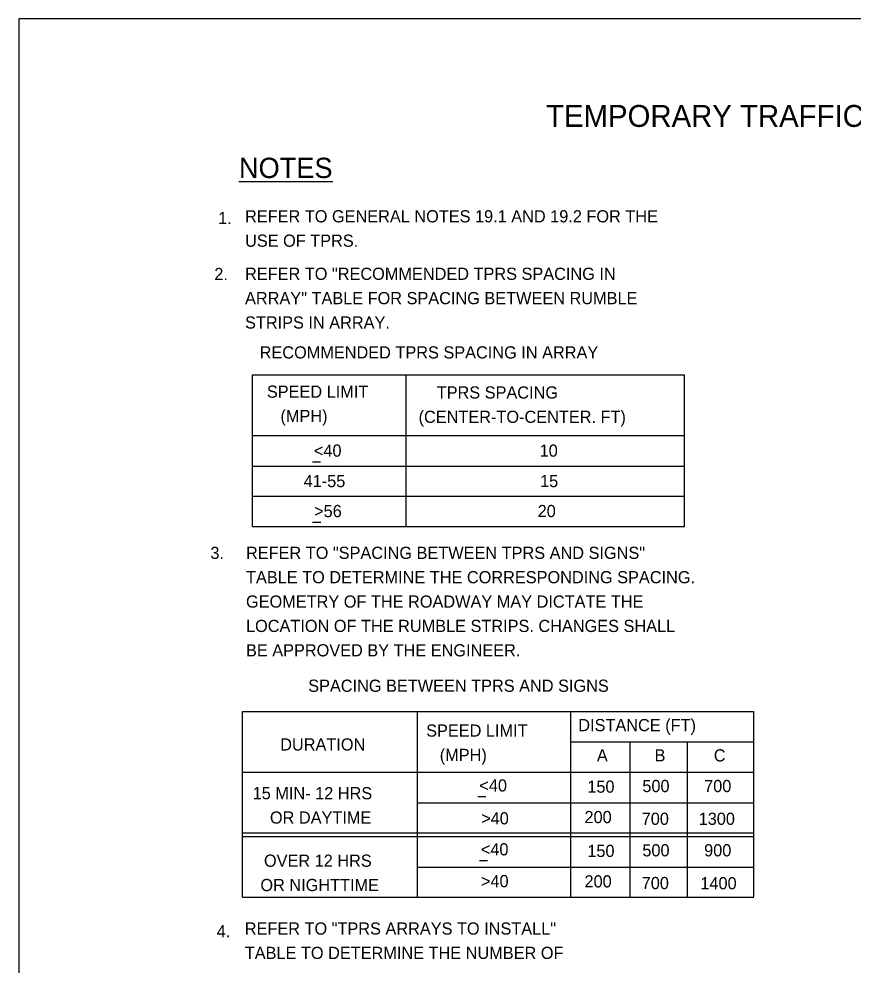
# Model space of a CAD drawing. Extents: x 0 to 1549163, y -476626 to 622136.
# Drawn here: x 11.438 to 15.545, y 12.007 to 16.667 of the extents above; entities that cross this region are included whole.
import ezdxf

# ---------------------------------------------------------------- set-up
doc = ezdxf.new("R2010")
doc.units = 0
for name, color, linetype in [('DETL-LINE', 7, 'Continuous'), ('DETL-NOTE', 7, 'Continuous'), ('DETL-TITL', 7, 'Continuous'), ('USER-CLIP', 7, 'Continuous')]:
    doc.layers.add(name, color=color, linetype=linetype)

msp = doc.modelspace()

# ---------------------------------------------------------------- linework, layer by layer
at = {"layer": 'DETL-LINE'}
msp.add_line((12.5213, 15.8667), (12.9832, 15.8667), dxfattribs=at)
at = {"layer": 'DETL-NOTE'}
for p, q in [((12.5884, 14.9152), (14.7157, 14.9152)), ((12.5884, 14.1675), (12.5884, 14.9152)), ((13.3438, 14.1675), (13.3438, 14.9152)), ((14.7157, 14.1675), (14.7157, 14.9152)), ((12.5884, 14.6152), (14.7157, 14.6152)), ((12.5884, 14.4652), (14.7157, 14.4652)), ((12.883, 14.4861), (12.9226, 14.4861)), ((12.5884, 14.3175), (14.7157, 14.3175)), ((12.5884, 14.1675), (14.7157, 14.1675)), ((12.884, 14.1884), (12.9236, 14.1884)), ((12.5379, 13.2567), (15.0562, 13.2567)), ((12.5379, 12.3424), (12.5379, 13.2567)), ((13.4002, 12.3424), (13.4002, 13.2567)), ((14.1556, 12.3424), (14.1556, 13.2567)), ((15.0562, 12.3457), (15.0562, 13.2567)), ((14.1556, 13.1073), (15.0562, 13.1073)), ((14.447, 12.3424), (14.447, 13.1073)), ((14.7291, 12.3424), (14.7291, 13.1073)), ((12.5379, 12.9567), (15.0562, 12.9567)), ((13.6977, 12.837), (13.7373, 12.837)), ((13.4002, 12.8067), (15.0562, 12.8067)), ((12.5379, 12.659), (15.0562, 12.659)), ((12.5379, 12.6401), (15.0562, 12.6401)), ((13.4002, 12.4901), (15.0562, 12.4901)), ((13.705, 12.5224), (13.7446, 12.5224)), ((12.5379, 12.3424), (15.0562, 12.3424))]:
    msp.add_line(p, q, dxfattribs=at)
at = {"layer": 'USER-CLIP'}
msp.add_lwpolyline([(19.9377, 16.6675), (11.4377, 16.6675), (11.4377, 5.6675), (19.9377, 5.6675)], close=True, dxfattribs=at)

# ---------------------------------------------------------------- texts
at = {"layer": 'DETL-NOTE'}
for s, height, p in [('NOTES', 0.1, (12.5213, 15.8838)), ('1.', 0.06, (12.4188, 15.6567)), ('REFER TO GENERAL NOTES 19.1 AND 19.2 FOR THE ', 0.06, (12.5512, 15.6654)), ('USE OF TPRS.', 0.06, (12.5512, 15.5454)), ('2.', 0.06, (12.3997, 15.3811)), ('REFER TO "RECOMMENDED TPRS SPACING IN ', 0.06, (12.5512, 15.3823)), ('ARRAY" TABLE FOR SPACING BETWEEN RUMBLE ', 0.06, (12.5512, 15.2623)), ('STRIPS IN ARRAY.', 0.06, (12.5512, 15.1423)), ('RECOMMENDED TPRS SPACING IN ARRAY', 0.06, (12.6231, 14.995)), ('SPEED LIMIT', 0.06, (12.6587, 14.8018)), ('    TPRS SPACING', 0.06, (13.4057, 14.7977)), ('   (MPH)', 0.06, (12.6587, 14.6818)), ('(CENTER-TO-CENTER. FT)', 0.06, (13.4057, 14.6777)), ('<40', 0.06, (12.8902, 14.5113)), ('10', 0.06, (14.0018, 14.5113)), ('41-55', 0.06, (12.8396, 14.3613)), ('15', 0.06, (14.0039, 14.3613)), ('>56', 0.06, (12.8912, 14.2136)), ('20', 0.06, (13.992, 14.2136)), ('3.', 0.06, (12.3805, 14.0075)), ('REFER TO "SPACING BETWEEN TPRS AND SIGNS" ', 0.06, (12.5559, 14.0078)), ('TABLE TO DETERMINE THE CORRESPONDING SPACING. ', 0.06, (12.5559, 13.8878)), ('GEOMETRY OF THE ROADWAY MAY DICTATE THE ', 0.06, (12.5559, 13.7678)), ('LOCATION OF THE RUMBLE STRIPS. CHANGES SHALL ', 0.06, (12.5559, 13.6478)), ('BE APPROVED BY THE ENGINEER.  ', 0.06, (12.5559, 13.5278)), ('SPACING BETWEEN TPRS AND SIGNS', 0.06, (12.8622, 13.3532)), ('SPEED LIMIT', 0.06, (13.443, 13.1324)), ('   DISTANCE (FT)', 0.06, (14.1253, 13.1593)), ('DURATION', 0.06, (12.7242, 13.0641)), ('   (MPH)', 0.06, (13.443, 13.0124)), ('A', 0.06, (14.2835, 13.0102)), ('B', 0.06, (14.5678, 13.0102)), ('C', 0.06, (14.8592, 13.0102)), ('<40', 0.06, (13.7049, 12.8622)), ('150', 0.06, (14.2366, 12.8563)), ('500', 0.06, (14.5076, 12.8593)), ('700', 0.06, (14.8118, 12.8593)), ('15 MIN- 12 HRS ', 0.06, (12.5887, 12.824)), ('OR DAYTIME', 0.06, (12.6737, 12.704)), ('>40', 0.06, (13.7138, 12.7003)), ('200', 0.06, (14.2227, 12.7063)), ('700', 0.06, (14.5044, 12.698)), ('1300', 0.06, (14.7849, 12.698)), ('<40', 0.06, (13.7122, 12.5476)), ('150', 0.06, (14.2366, 12.5397)), ('500', 0.06, (14.5076, 12.5427)), ('900', 0.06, (14.8118, 12.5427)), ('OVER 12 HRS ', 0.06, (12.6443, 12.4916)), ('>40', 0.06, (13.7128, 12.3909)), ('200', 0.06, (14.2227, 12.3897)), ('OR NIGHTTIME', 0.06, (12.6268, 12.3716)), ('700', 0.06, (14.5044, 12.3814)), ('1400', 0.06, (14.7933, 12.3804)), ('REFER TO "TPRS ARRAYS TO INSTALL" ', 0.06, (12.5499, 12.1573)), ('4.', 0.06, (12.4118, 12.1443)), ('TABLE TO DETERMINE THE NUMBER OF ', 0.06, (12.5499, 12.0373))]:
    msp.add_text(s, height=height, dxfattribs=at).set_placement(p)
at = {"layer": 'DETL-TITL'}
msp.add_text('TEMPORARY TRAFFIC CONTROL TYPICAL APPLICATION', height=0.108, dxfattribs=at).set_placement((14.0336, 16.1357))

doc.saveas('drawing.dxf')
